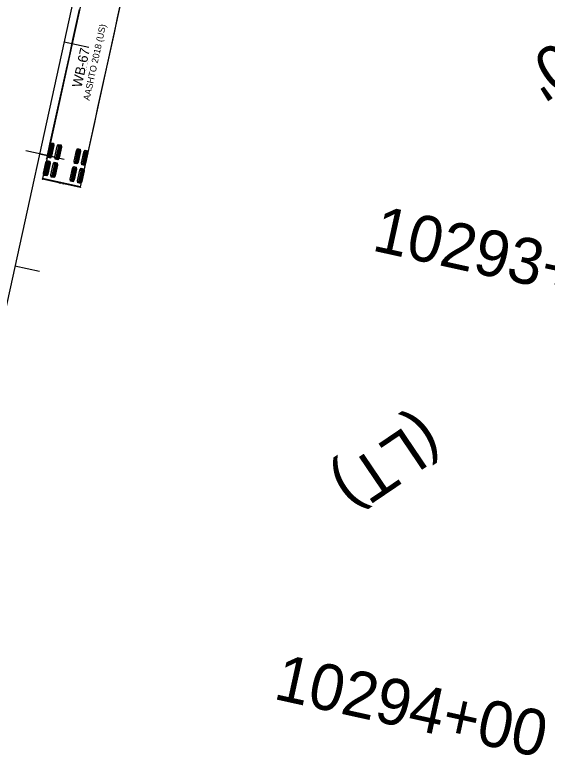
# Model space of a CAD drawing. Extents: x -69 to 14108008, y -6 to 8640172.
# Drawn here: x 14107700.6 to 14107816.5, y 8639555.2 to 8639717.5 of the extents above; entities that cross this region are included whole.
import ezdxf

# ---------------------------------------------------------------- set-up
doc = ezdxf.new("R2010")
doc.units = 0
for name, color, linetype in [('Alignment', 7, 'Continuous'), ('AutoTurn3', 7, 'Continuous'), ('TextAlignment', 7, 'Continuous'), ('TextAlignmentLrg', 7, 'Continuous'), ('TextAlignmentSml', 7, 'Continuous')]:
    doc.layers.add(name, color=color, linetype=linetype)

msp = doc.modelspace()

# ---------------------------------------------------------------- linework, layer by layer
at = {"layer": 'Alignment'}
msp.add_line((14107732.61, 8639808.61), (14107547.95, 8638968.47), dxfattribs=at)
at = {"layer": 'AutoTurn3'}
for p, q in [((14107708.5, 8639689.67), (14107707.79, 8639686.44)), ((14107708.72, 8639689.62), (14107708.01, 8639686.39)), ((14107708.94, 8639689.57), (14107708.23, 8639686.34)), ((14107710.11, 8639689.31), (14107709.4, 8639686.09)), ((14107710.33, 8639689.26), (14107709.62, 8639686.04)), ((14107710.55, 8639689.21), (14107709.85, 8639685.99)), ((14107714.29, 8639688.39), (14107713.58, 8639685.17)), ((14107714.51, 8639688.34), (14107713.81, 8639685.12)), ((14107714.74, 8639688.29), (14107714.03, 8639685.07)), ((14107715.9, 8639688.04), (14107715.19, 8639684.81)), ((14107716.13, 8639687.99), (14107715.42, 8639684.77)), ((14107716.35, 8639687.94), (14107715.64, 8639684.72)), ((14107707.64, 8639685.76), (14107706.93, 8639682.54)), ((14107707.86, 8639685.71), (14107707.15, 8639682.49)), ((14107708.08, 8639685.66), (14107707.38, 8639682.44)), ((14107709.25, 8639685.4), (14107708.54, 8639682.18)), ((14107709.47, 8639685.36), (14107708.76, 8639682.13)), ((14107709.7, 8639685.31), (14107708.99, 8639682.08)), ((14107713.43, 8639684.49), (14107712.72, 8639681.26)), ((14107713.66, 8639684.44), (14107712.95, 8639681.21)), ((14107713.88, 8639684.39), (14107713.17, 8639681.16)), ((14107715.04, 8639684.13), (14107714.33, 8639680.91)), ((14107715.27, 8639684.08), (14107714.56, 8639680.86)), ((14107715.49, 8639684.03), (14107714.78, 8639680.81)), ((14107714.85, 8639680.07), (14107706.55, 8639681.89)), ((14107710.43, 8639680.97), (14107710.17, 8639681.03)), ((14107710.43, 8639680.97), (14107710.94, 8639680.86)), ((14107710.69, 8639680.91), (14107710.7, 8639680.98)), ((14107711.21, 8639680.8), (14107710.95, 8639680.85))]:
    msp.add_line(p, q, dxfattribs=at)
for points in [[(14107714.82, 8639680), (14107714.84, 8639680), (14107714.85, 8639680.07), (14107716.07, 8639685.6), (14107726.2, 8639731.69), (14107722.05, 8639732.61), (14107717.9, 8639733.52), (14107707.77, 8639687.43), (14107706.55, 8639681.89), (14107706.54, 8639681.82), (14107706.56, 8639681.82)], [(14107715.79, 8639684.33), (14107716.5, 8639687.58), (14107717.22, 8639690.83), (14107717.94, 8639694.09), (14107718.65, 8639697.34), (14107719.37, 8639700.6), (14107720.08, 8639703.85), (14107720.8, 8639707.1), (14107721.51, 8639710.36), (14107722.23, 8639713.61), (14107722.94, 8639716.87), (14107723.66, 8639720.12)], [(14107707.49, 8639686.15), (14107708.2, 8639689.4), (14107708.92, 8639692.66), (14107709.63, 8639695.91), (14107710.35, 8639699.17), (14107711.06, 8639702.42), (14107711.78, 8639705.67), (14107712.49, 8639708.93), (14107713.21, 8639712.18), (14107713.93, 8639715.44), (14107714.64, 8639718.69)], [(14107706.58, 8639681.81), (14107706.58, 8639681.81), (14107710.13, 8639681.03), (14107710.17, 8639681.03), (14107710.15, 8639680.96), (14107710.15, 8639680.96), (14107710.42, 8639680.9)], [(14107710.93, 8639680.79), (14107711.19, 8639680.73), (14107711.19, 8639680.73), (14107711.21, 8639680.8), (14107711.24, 8639680.79), (14107714.79, 8639680.01), (14107714.79, 8639680.01)]]:
    msp.add_lwpolyline(points, dxfattribs=at)
for points in [[(14107708.44, 8639689.68), (14107709, 8639689.56), (14107709.07, 8639689.07), (14107708.56, 8639686.75), (14107708.29, 8639686.33), (14107707.73, 8639686.45), (14107707.66, 8639686.94), (14107708.17, 8639689.26)], [(14107710.05, 8639689.32), (14107710.61, 8639689.2), (14107710.68, 8639688.71), (14107710.17, 8639686.39), (14107709.9, 8639685.98), (14107709.34, 8639686.1), (14107709.27, 8639686.59), (14107709.78, 8639688.91)], [(14107714.23, 8639688.4), (14107714.79, 8639688.28), (14107714.86, 8639687.79), (14107714.35, 8639685.47), (14107714.08, 8639685.06), (14107713.53, 8639685.18), (14107713.46, 8639685.67), (14107713.97, 8639687.99)], [(14107715.85, 8639688.05), (14107716.4, 8639687.93), (14107716.47, 8639687.44), (14107715.96, 8639685.12), (14107715.7, 8639684.7), (14107715.14, 8639684.83), (14107715.07, 8639685.32), (14107715.58, 8639687.64)], [(14107707.58, 8639685.77), (14107708.14, 8639685.65), (14107708.21, 8639685.16), (14107707.7, 8639682.84), (14107707.43, 8639682.43), (14107706.87, 8639682.55), (14107706.8, 8639683.04), (14107707.31, 8639685.36)], [(14107709.19, 8639685.42), (14107709.75, 8639685.29), (14107709.82, 8639684.81), (14107709.31, 8639682.49), (14107709.04, 8639682.07), (14107708.48, 8639682.19), (14107708.41, 8639682.68), (14107708.92, 8639685)], [(14107713.38, 8639684.5), (14107713.93, 8639684.37), (14107714, 8639683.89), (14107713.49, 8639681.57), (14107713.23, 8639681.15), (14107712.67, 8639681.27), (14107712.6, 8639681.76), (14107713.11, 8639684.08)], [(14107714.99, 8639684.14), (14107715.55, 8639684.02), (14107715.62, 8639683.53), (14107715.11, 8639681.21), (14107714.84, 8639680.8), (14107714.28, 8639680.92), (14107714.21, 8639681.41), (14107714.72, 8639683.73)]]:
    msp.add_lwpolyline(points, close=True, dxfattribs=at)
for centre, radius in [((14107707.49, 8639686.15), 0.0417), ((14107715.79, 8639684.33), 0.0417), ((14107706.56, 8639681.78), 0.0266), ((14107714.8, 8639679.97), 0.0266)]:
    msp.add_circle(centre, radius, dxfattribs=at)
for centre, radius, start, end in [((14107706.56, 8639681.78), 0.0363, 96.6806, 57.842), ((14107710.42, 8639680.93), 0.0353, 80.9394, 259.289), ((14107710.42, 8639680.93), 0.0352, 257.6284, 76.6289), ((14107710.94, 8639680.82), 0.0352, 78.5775, 257.5779), ((14107710.94, 8639680.82), 0.0354, 261.8947, 74.0802), ((14107714.38, 8639678.03), 2.02, 77.6032, 78.2869)]:
    msp.add_arc(centre, radius, start, end, dxfattribs=at)
at = {"layer": 'TextAlignmentLrg'}
msp.add_line((14107705.94, 8639687.26), (14107711.27, 8639686.08), dxfattribs=at)
at = {"layer": 'TextAlignmentSml'}
for p, q in [((14107711.31, 8639711.67), (14107716.64, 8639710.5)), ((14107708.93, 8639686.6), (14107702.95, 8639687.91)), ((14107700.57, 8639662.84), (14107705.9, 8639661.67))]:
    msp.add_line(p, q, dxfattribs=at)

# ---------------------------------------------------------------- texts
at = {"layer": 'AutoTurn3'}
for s, height, p in [('AASHTO 2018 (US)', 1.4167, (14107716.8, 8639698.78)), ('WB-67', 2.125, (14107715.06, 8639701.57)), ('(c) 2023 Transoft Solutions, Inc. All rights reserved.', 0.085, (14107716.03, 8639705.02))]:
    msp.add_text(s, height=height, rotation=77.6032, dxfattribs=at).set_placement(p)
at = {"layer": 'TextAlignment'}
for s, p in [("120.00'", (14107846.63, 8639731.03)), (' (LT)', (14107792.38, 8639632.64))]:
    msp.add_text(s, height=10.02, rotation=214.0771, dxfattribs=at).set_placement(p)
at = {"layer": 'TextAlignmentSml'}
for s, p in [('10293+00', (14107778.11, 8639666.26)), ('10294+00', (14107756.65, 8639568.59))]:
    msp.add_text(s, height=10.02, rotation=347.6032, dxfattribs=at).set_placement(p)

doc.saveas('drawing.dxf')
